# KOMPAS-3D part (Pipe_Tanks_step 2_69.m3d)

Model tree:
1. X Axis
2. Y Axis
3. Z Axis  (labels: Valve Dy 50; Pipe Dn 50)
     Òîëùèíà ñòåíêè 1 = 1

Referenced files in C:\Documents and Settings\kashirsky\Мои документы\Camtasia Studio\Pipelines3D\Tanks\: Tanks_step 2.a3d
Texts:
  Pipe Dn 50
  Steel ASTM A295
  Three Point Plane
  Plane at Angle
  Line and Point Plane
  Axis through Two Vertices
  Axis of Feature
  Axis of Conical Surface
  Axis through Edge
  Trim by Surface
  Trim by Sketch
  Feature with No History
  Intersection Axis of Two Planes
  Two Line Plane
  Line and Face Plane
  Bend by line
  Hole in sheet body
  Cut in sheet body
  Point in CM
  Linear Dimension from Line to Point
  Surface Finish Symbol
  Geometric Tolerance Symbol
  Leader #1
  Leader #2
  Leader #3
  Shape Deviations and Datum
  Node point number
  Mark of coordination axis
  Node point designation
  Mark/Reference designation with leader
  Mark/reference designation on line
  Mark/Reference designation without leader
  Valve Dy 50
  Plane of section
